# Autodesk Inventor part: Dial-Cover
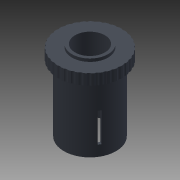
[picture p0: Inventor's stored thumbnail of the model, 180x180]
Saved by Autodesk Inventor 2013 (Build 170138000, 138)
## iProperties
Shininess: 64.0
Length Units: 11272
Angle Units: 11279
Time Units: 11290
Mass Units: 11286
Length Display Precision: 3
Angle Display Precision: 2
Compacted: True
Created: 2001-11
Part Number: Dial-Cover
Document SubType Name: Modeling
Designer: Autodesk, Inc.
Mass: 5.42511 g
Surface Area: 53.7996 cm^2
Volume: 5.42511 cm^3
Density: 1 g/cm^3
Material: Generic
Density: 0.0
Volumn: 0.0
Area: 0.0
PropertySet Name: Model Information
Control State: 0
Master: False
Checked Out: False
Author: Autodesk, Inc.
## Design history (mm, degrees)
sketch "Sketch2"
  geometry: L1 (10.006, 24.13)-(6.45, 24.13); L2 (10.006, 0)-(10.006, 24.13); L3 (11.276, 0)-(10.006, 0); L4 (11.276, 28.575)-(11.276, 0); L5 (13.816, 28.575)-(11.276, 28.575); L6 (13.816, 33.274)-(13.816, 28.575); L7 (7.784, 33.274)-(13.816, 33.274); L8 (7.784, 34.544)-(7.784, 33.274); L9 (6.45, 34.544)-(7.784, 34.544); L10 (6.45, 24.13)-(6.45, 34.544); L11 (0, 0)-(0, 34.056); 1 further point
  constraints: 22 end point, 5 horizontal, 5 vertical, 1 coincident, 1 horizontal alignment
  dimensions: "d15" = 12.90092 diameter of L10 L11; "d16" = 15.56792 diameter of L8 L11; "d17" = 10.414 distance of L1.end L9.start; "d18" = 4.699 distance of L6.start L5.start; "d19" = 6.0325 distance of L7.start L6.start; "d20" = 2.54 distance of L5.start L4.start; "d21" = 28.575 distance of L4.start L3.start; "d22" = 20.01292 diameter of L2 L11; "d23" = 1.27 distance of L8.start L7.start
revolve "RevolutionFull1" sketch "Sketch2" stored, may be unused: angle "d0" = 360 deg
sketch "Sketch3"
  geometry: L1 (-0.635, 17.287)-(0.635, 17.287); L2 (0.635, 17.287)-(0.635, 4.587); L3 (-0.635, 4.587)-(0.635, 4.587); L4 (-0.635, 17.287)-(-0.635, 4.587); L5 (0, -1.15)-(0, 39.011) reference; 1 further point
  constraints: 8 end point, 2 horizontal, 2 vertical, 1 midpoint, 1 point on line
  dimensions: "d24" = 12.7 distance of L1.end L2.end; "d25" = 1.27 distance of L1.start L1.end
extrude "ExtrusionMidplane1" cut sketch "Sketch3" stored distance "d1" = 127; taper "d2" = 0 deg
pattern_circular "PolarArray1" dims angle "d7" = 360 deg
sketch "Sketch6"
  geometry: C1 r 1.27 at (-14.854, 0)
  constraints: 1 centre point
  dimensions: "d9" = 2.54 diameter of C1
extrude "ExtrusionToPlane1" cut sketch "Sketch6" stored distance "d10" = 3.302; taper "d11" = 0 deg
node "Sketch7"
body "Solid1"
pattern_circular "Circular Pattern3" dims angle "d28" = 360 deg
other parameters: "d3" = 0, "d4" = 0, "d8" = 2.54 (derived)
